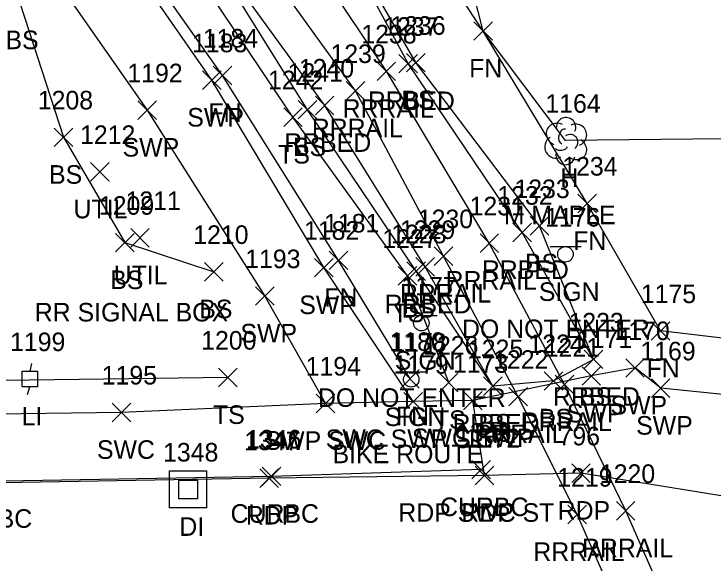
# Model space of a CAD drawing. Extents: x 1715662 to 1717487, y 887396 to 890004.
# Drawn here: x 1716350.8 to 1716426.1, y 888258 to 888317.1 of the extents above; entities that cross this region are included whole.
import ezdxf

# ---------------------------------------------------------------- set-up
doc = ezdxf.new("R2010")
doc.units = 0
for name, color, linetype in [('D_A', 7, 'Continuous'), ('D_I', 7, 'Continuous'), ('DS', 7, 'Continuous'), ('L_A', 7, 'Continuous'), ('L_C', 7, 'Continuous'), ('L_I', 7, 'Continuous'), ('L_TIC', 7, 'Continuous'), ('LELB', 7, 'Continuous'), ('LFNC', 7, 'Continuous'), ('LSOGP', 7, 'Continuous'), ('LTD', 7, 'Continuous'), ('P_A', 7, 'Continuous'), ('P_I', 7, 'Continuous'), ('P_TIC', 7, 'Continuous'), ('PET', 7, 'Continuous'), ('R_A', 7, 'Continuous'), ('R_I', 7, 'Continuous'), ('R_TIC', 7, 'Continuous'), ('RC', 7, 'Continuous'), ('RR', 7, 'Continuous'), ('RRB', 7, 'Continuous'), ('RSW', 7, 'Continuous'), ('S_A', 7, 'Continuous'), ('S_C', 7, 'Continuous'), ('S_I', 7, 'Continuous'), ('SSGN', 7, 'Continuous'), ('U_A', 7, 'Continuous'), ('U_C', 7, 'Continuous'), ('U_I', 7, 'Continuous'), ('UDEFAULT', 7, 'Continuous'), ('ULP', 7, 'Continuous')]:
    doc.layers.add(name, color=color, linetype=linetype)

msp = doc.modelspace()

# ---------------------------------------------------------------- linework, layer by layer
at = {"layer": 'DS'}
for p, q in [((1716367.581, 888267.933), (1716371.581, 888267.933)), ((1716367.581, 888263.933), (1716367.581, 888267.933)), ((1716371.581, 888267.933), (1716371.581, 888263.933)), ((1716368.581, 888264.933), (1716368.581, 888266.933)), ((1716368.581, 888266.933), (1716370.581, 888266.933)), ((1716370.581, 888266.933), (1716370.581, 888264.933)), ((1716369.586, 888265.934), (1716369.586, 888265.934)), ((1716369.586, 888265.934), (1716369.586, 888265.934)), ((1716370.581, 888264.933), (1716368.581, 888264.933)), ((1716371.581, 888263.933), (1716367.581, 888263.933))]:
    msp.add_line(p, q, dxfattribs=at)
at = {"layer": 'L_TIC'}
for points in [[(1716400.348, 888314.282), (1716402.348, 888316.282)], [(1716402.348, 888314.282), (1716400.348, 888316.282)], [(1716393.099, 888310.877), (1716395.099, 888312.877)], [(1716395.099, 888310.877), (1716393.099, 888312.877)], [(1716372.292, 888309.5), (1716374.292, 888311.5)], [(1716374.292, 888309.5), (1716372.292, 888311.5)], [(1716381.432, 888305.814), (1716383.432, 888307.814)], [(1716383.432, 888305.814), (1716381.432, 888307.814)], [(1716379.872, 888305.015), (1716381.872, 888307.015)], [(1716381.872, 888305.015), (1716379.872, 888307.015)], [(1716355.181, 888302.84), (1716357.181, 888304.84)], [(1716357.181, 888302.84), (1716355.181, 888304.84)], [(1716411.543, 888295.715), (1716413.543, 888297.715)], [(1716413.543, 888295.715), (1716411.543, 888297.715)], [(1716406.394, 888293.296), (1716408.394, 888295.296)], [(1716408.394, 888293.296), (1716406.394, 888295.296)], [(1716361.768, 888291.5), (1716363.768, 888293.5)], [(1716363.768, 888291.5), (1716361.768, 888293.5)], [(1716384.773, 888289.591), (1716386.773, 888291.591)], [(1716386.773, 888289.591), (1716384.773, 888291.591)], [(1716371.35, 888288.359), (1716373.35, 888290.359)], [(1716373.35, 888288.359), (1716371.35, 888290.359)], [(1716392.186, 888287.936), (1716394.186, 888289.936)], [(1716394.186, 888287.936), (1716392.186, 888289.936)], [(1716393.13, 888288.432), (1716395.13, 888290.432)], [(1716395.13, 888288.432), (1716393.13, 888290.432)], [(1716419.433, 888281.989), (1716421.433, 888283.989)], [(1716421.433, 888281.989), (1716419.433, 888283.989)], [(1716412.209, 888278.935), (1716414.209, 888280.935)], [(1716414.209, 888278.935), (1716412.209, 888280.935)], [(1716412.209, 888278.935), (1716414.209, 888280.935)], [(1716414.209, 888278.935), (1716412.209, 888280.935)], [(1716372.854, 888276.981), (1716374.854, 888278.981)], [(1716374.854, 888276.981), (1716372.854, 888278.981)], [(1716392.469, 888276.838), (1716394.469, 888278.838)], [(1716394.469, 888276.838), (1716392.469, 888278.838)], [(1716407.898, 888276.608), (1716409.898, 888278.608)], [(1716409.898, 888276.608), (1716407.898, 888278.608)], [(1716396.626, 888276.445), (1716398.626, 888278.445)], [(1716398.626, 888276.445), (1716396.626, 888278.445)], [(1716401.391, 888276.055), (1716403.391, 888278.055)], [(1716403.391, 888276.055), (1716401.391, 888278.055)]]:
    msp.add_lwpolyline(points, dxfattribs=at)
at = {"layer": 'LELB'}
for points in [[(1716397.626, 888277.445), (1716393.186, 888288.936), (1716380.872, 888306.015), (1716367.189, 888326.46), (1716357.094, 888343.322)], [(1716339.091, 888339.822), (1716351.492, 888318.326), (1716356.181, 888303.84), (1716362.768, 888292.5), (1716372.35, 888289.359)], [(1716373.854, 888277.981), (1716341.818, 888277.563), (1716337.074, 888296.382), (1716336.988, 888312.112), (1716344.519, 888320.79), (1716334.379, 888337.453)], [(1716413.209, 888279.935), (1716407.394, 888294.296), (1716394.099, 888311.877), (1716381.094, 888334.374)], [(1716413.209, 888279.935), (1716408.898, 888277.608), (1716402.391, 888277.055), (1716394.13, 888289.432), (1716382.432, 888306.814), (1716369.213, 888328.084)]]:
    msp.add_lwpolyline(points, dxfattribs=at)
at = {"layer": 'LFNC'}
for points in [[(1716443.098, 888280.317), (1716420.433, 888282.989), (1716412.543, 888296.715), (1716401.348, 888315.282), (1716386.51, 888337.853), (1716374.785, 888353.899), (1716358.025, 888375.078), (1716341.376, 888394.001), (1716322.754, 888413.454), (1716303.71, 888431.095), (1716282.224, 888449.189), (1716263.808, 888463.099), (1716243.953, 888476.997), (1716231.603, 888485.189), (1716232.765, 888492.604)], [(1716393.469, 888277.838), (1716385.773, 888290.591), (1716373.292, 888310.5), (1716357.546, 888332.847), (1716346.753, 888347.139), (1716337.883, 888358.435), (1716321.742, 888376.902), (1716305.606, 888393.218), (1716286.544, 888410.885), (1716268.192, 888426.034), (1716248.019, 888441.452), (1716229.393, 888453.959), (1716214.648, 888463.044)]]:
    msp.add_lwpolyline(points, dxfattribs=at)
at = {"layer": 'LSOGP'}
msp.add_lwpolyline([(1716469.007, 888433.308), (1716446.639, 888397.104), (1716439.784, 888394.85), (1716438.641, 888388.155), (1716443.71, 888383.152), (1716446.38, 888343.601), (1716442.786, 888319.775), (1716434.149, 888303.757), (1716410.201, 888303.478), (1716401.342, 888315.278), (1716398.071, 888328.134), (1716386.509, 888337.85), (1716374.78, 888353.896), (1716358.023, 888375.075), (1716341.376, 888394), (1716322.749, 888413.449)], dxfattribs=at)
at = {"layer": 'LTD'}
msp.add_line((1716410.207, 888303.482), (1716410.207, 888303.482), dxfattribs=at)
msp.add_line((1716410.207, 888303.482), (1716410.207, 888303.482), dxfattribs=at)
msp.add_arc((1716410.254, 888304.916), 1.047, 335.52715, 180.95627, dxfattribs=at)
for centre, major_axis, ratio, start_param, end_param in [((1716409.416, 888304.148), (1.21, -0.512), 0.895232, 1.570796, 4.712389), ((1716411.249, 888304.065), (-1.141, -0.483), 0.949671, 1.570796, 4.712389), ((1716409.999, 888303.94), (-0.208, -0.792), 0.645439, 3.141593, 6.283185), ((1716410.707, 888303.315), (-0.5, 0.667), 0.989748, 3.141593, 6.283185), ((1716409.124, 888302.773), (0.584, -1.042), 0.959034, 3.141593, 6.283185), ((1716411.207, 888302.649), (-1.09, 0.792), 0.841452, 1.570796, 4.712389), ((1716409.749, 888302.732), (-0.625, -0.083), 0.423636, 0, 3.141593), ((1716410.208, 888301.982), (0.265, 1.061), 0.942809, 1.570796, 4.712389)]:
    msp.add_ellipse(centre, major_axis=major_axis, ratio=ratio, start_param=start_param, end_param=end_param, dxfattribs=at)
at = {"layer": 'P_TIC'}
for points in [[(1716377.307, 888266.153), (1716379.307, 888268.153)], [(1716379.307, 888266.153), (1716377.307, 888268.153)], [(1716400.494, 888266.443), (1716402.494, 888268.443)], [(1716402.494, 888266.443), (1716400.494, 888268.443)], [(1716410.867, 888266.674), (1716412.867, 888268.674)], [(1716412.867, 888266.674), (1716410.867, 888268.674)]]:
    msp.add_lwpolyline(points, dxfattribs=at)
at = {"layer": 'PET'}
msp.add_lwpolyline([(1716527, 888260.728), (1716516.575, 888259.254), (1716502.433, 888259.092), (1716473.824, 888260.93), (1716440.241, 888263.084), (1716411.867, 888267.674), (1716401.494, 888267.443), (1716378.307, 888267.153), (1716347.525, 888266.611), (1716339.044, 888266.533), (1716305.127, 888265.54), (1716291.61, 888264.06), (1716269.77, 888261.49)], dxfattribs=at)
at = {"layer": 'R_TIC'}
for points in [[(1716392.281, 888310.771), (1716394.281, 888312.771)], [(1716394.281, 888310.771), (1716392.281, 888312.771)], [(1716389.919, 888309.944), (1716391.919, 888311.944)], [(1716391.919, 888309.944), (1716389.919, 888311.944)], [(1716371.137, 888308.995), (1716373.137, 888310.995)], [(1716373.137, 888308.995), (1716371.137, 888310.995)], [(1716386.606, 888307.839), (1716388.606, 888309.839)], [(1716388.606, 888307.839), (1716386.606, 888309.839)], [(1716383.284, 888306.273), (1716385.284, 888308.273)], [(1716385.284, 888306.273), (1716383.284, 888308.273)], [(1716364.176, 888305.762), (1716366.176, 888307.762)], [(1716366.176, 888305.762), (1716364.176, 888307.762)], [(1716404.549, 888292.581), (1716406.549, 888294.581)], [(1716406.549, 888292.581), (1716404.549, 888294.581)], [(1716401.001, 888291.439), (1716403.001, 888293.439)], [(1716403.001, 888291.439), (1716401.001, 888293.439)], [(1716396.082, 888290.053), (1716398.082, 888292.053)], [(1716398.082, 888290.053), (1716396.082, 888292.053)], [(1716383.185, 888288.805), (1716385.185, 888290.805)], [(1716385.185, 888288.805), (1716383.185, 888290.805)], [(1716394.087, 888288.895), (1716396.087, 888290.895)], [(1716396.087, 888288.895), (1716394.087, 888290.895)], [(1716376.856, 888285.753), (1716378.856, 888287.753)], [(1716378.856, 888285.753), (1716376.856, 888287.753)], [(1716412.209, 888278.935), (1716414.209, 888280.935)], [(1716414.209, 888278.935), (1716412.209, 888280.935)], [(1716416.678, 888278.005), (1716418.678, 888280.005)], [(1716418.678, 888278.005), (1716416.678, 888280.005)], [(1716411.978, 888277.145), (1716413.978, 888279.145)], [(1716413.978, 888277.145), (1716411.978, 888279.145)], [(1716401.391, 888276.055), (1716403.391, 888278.055)], [(1716403.391, 888276.055), (1716401.391, 888278.055)], [(1716409.086, 888276.215), (1716411.086, 888278.215)], [(1716411.086, 888276.215), (1716409.086, 888278.215)], [(1716419.44, 888275.827), (1716421.44, 888277.827)], [(1716421.44, 888275.827), (1716419.44, 888277.827)], [(1716392.811, 888274.383), (1716394.811, 888276.383)], [(1716394.811, 888274.383), (1716392.811, 888276.383)], [(1716392.811, 888274.383), (1716394.811, 888276.383)], [(1716394.811, 888274.383), (1716392.811, 888276.383)], [(1716399.217, 888274.488), (1716401.217, 888276.488)], [(1716401.217, 888274.488), (1716399.217, 888276.488)], [(1716399.217, 888274.488), (1716401.217, 888276.488)], [(1716401.217, 888274.488), (1716399.217, 888276.488)], [(1716404.098, 888274.915), (1716406.098, 888276.915)], [(1716406.098, 888274.915), (1716404.098, 888276.915)], [(1716383.363, 888274.19), (1716385.363, 888276.19)], [(1716385.363, 888274.19), (1716383.363, 888276.19)], [(1716383.363, 888274.19), (1716385.363, 888276.19)], [(1716385.363, 888274.19), (1716383.363, 888276.19)], [(1716361.415, 888273.225), (1716363.415, 888275.225)], [(1716363.415, 888273.225), (1716361.415, 888275.225)], [(1716400.116, 888267.058), (1716402.116, 888269.058)], [(1716402.116, 888267.058), (1716400.116, 888269.058)], [(1716377.574, 888266.336), (1716379.574, 888268.336)], [(1716379.574, 888266.336), (1716377.574, 888268.336)], [(1716400.494, 888266.443), (1716402.494, 888268.443)], [(1716402.494, 888266.443), (1716400.494, 888268.443)], [(1716410.445, 888262.23), (1716412.445, 888264.23)], [(1716412.445, 888262.23), (1716410.445, 888264.23)], [(1716415.677, 888262.628), (1716417.677, 888264.628)], [(1716417.677, 888262.628), (1716415.677, 888264.628)]]:
    msp.add_lwpolyline(points, dxfattribs=at)
at = {"layer": 'RC'}
msp.add_lwpolyline([(1716401.116, 888268.058), (1716378.574, 888267.336), (1716347.715, 888266.797), (1716339.127, 888266.78), (1716337.533, 888268.537)], dxfattribs=at)
at = {"layer": 'RR'}
for points in [[(1716436.006, 888215.337), (1716430.823, 888230.215), (1716426.348, 888241.635), (1716416.677, 888263.628), (1716410.086, 888277.215), (1716402.001, 888292.439), (1716390.919, 888310.944), (1716376.876, 888331.991), (1716364.819, 888348.018), (1716349.123, 888367.789), (1716332.642, 888386.349), (1716315.07, 888404.654), (1716296.205, 888422.302), (1716278.069, 888437.86), (1716256.9, 888454.27), (1716238.515, 888467.25), (1716223.556, 888476.476), (1716202.573, 888488.846), (1716178.442, 888501.208), (1716153.561, 888512.412), (1716127.616, 888522.226), (1716099.939, 888531.037), (1716073.491, 888537.688), (1716046.147, 888542.834)], [(1716430.72, 888215.397), (1716425.304, 888230.283), (1716421.076, 888241.431), (1716411.445, 888263.23), (1716405.098, 888275.915), (1716397.082, 888291.053), (1716387.606, 888308.839), (1716372.559, 888329.716), (1716360.984, 888345.241), (1716345.129, 888364.699), (1716328.621, 888383.271), (1716311.711, 888401.255), (1716292.491, 888418.83), (1716274.069, 888433.953), (1716254.21, 888450.025), (1716235.796, 888462.901), (1716221.101, 888472.304), (1716200.717, 888484.158), (1716175.893, 888496.909), (1716151.922, 888507.643), (1716125.759, 888517.559), (1716098.568, 888526.188), (1716072.377, 888532.71), (1716045.904, 888537.783)]]:
    msp.add_lwpolyline(points, dxfattribs=at)
at = {"layer": 'RRB'}
for points in [[(1716413.209, 888279.935), (1716405.549, 888293.581), (1716393.281, 888311.771), (1716381.094, 888334.374), (1716367.434, 888349.07), (1716353.599, 888371.628), (1716336.573, 888389.892), (1716318.547, 888409.005), (1716299.812, 888426.157), (1716280.583, 888443.639), (1716260.294, 888458.826), (1716240.844, 888471.367), (1716225.46, 888478.919)], [(1716402.391, 888277.055), (1716395.087, 888289.895), (1716384.284, 888307.273), (1716369.213, 888328.084), (1716357.094, 888343.322), (1716343.151, 888363.152), (1716325.893, 888380.56), (1716309.064, 888397.835), (1716289.633, 888415.582), (1716271.912, 888431.207), (1716252.081, 888447.529), (1716234.746, 888461.341), (1716219.561, 888469.487)]]:
    msp.add_lwpolyline(points, dxfattribs=at)
at = {"layer": 'RSW'}
for points in [[(1716476.683, 888425.515), (1716468.032, 888388.369), (1716466.749, 888382.232), (1716461.599, 888360.08), (1716450.017, 888310.475), (1716443.843, 888279.7), (1716440.9, 888274.749), (1716420.44, 888276.827), (1716417.678, 888279.005), (1716412.978, 888278.145), (1716400.217, 888275.488)], [(1716393.811, 888275.383), (1716384.185, 888289.805), (1716372.137, 888309.995), (1716356.589, 888332.413), (1716345.321, 888346.931)], [(1716340.33, 888341.332), (1716352.583, 888324.821), (1716365.176, 888306.762), (1716377.856, 888286.753), (1716384.363, 888275.19)], [(1716401.494, 888267.443), (1716400.217, 888275.488), (1716393.811, 888275.383), (1716384.363, 888275.19), (1716362.415, 888274.225), (1716346.221, 888273.995), (1716335.781, 888273.932)]]:
    msp.add_lwpolyline(points, dxfattribs=at)
at = {"layer": 'SSGN'}
for p, q in [((1716408.543, 888292.077), (1716411.877, 888292.077)), ((1716410.19, 888291.244), (1716410.19, 888291.244)), ((1716393.041, 888284.668), (1716396.374, 888284.668)), ((1716394.688, 888283.835), (1716394.688, 888283.835)), ((1716391.95, 888278.607), (1716395.283, 888278.607)), ((1716393.597, 888277.774), (1716393.597, 888277.774))]:
    msp.add_line(p, q, dxfattribs=at)
for centre in [(1716410.19, 888291.244), (1716394.688, 888283.835), (1716393.597, 888277.774)]:
    msp.add_circle(centre, 0.833, dxfattribs=at)
at = {"layer": 'UDEFAULT'}
for points in [[(1716359.085, 888299.12), (1716361.085, 888301.12)], [(1716361.085, 888299.12), (1716359.085, 888301.12)], [(1716363.409, 888292.01), (1716365.409, 888294.01)], [(1716365.409, 888292.01), (1716363.409, 888294.01)]]:
    msp.add_lwpolyline(points, dxfattribs=at)
at = {"layer": 'ULP'}
for p, q in [((1716352.727, 888279.487), (1716352.56, 888278.653)), ((1716351.727, 888276.987), (1716351.727, 888278.653)), ((1716351.727, 888278.653), (1716353.393, 888278.653)), ((1716353.393, 888278.653), (1716353.393, 888276.987)), ((1716352.56, 888277.82), (1716352.56, 888277.82)), ((1716353.393, 888276.987), (1716351.727, 888276.987)), ((1716352.31, 888276.153), (1716352.56, 888276.987))]:
    msp.add_line(p, q, dxfattribs=at)

# ---------------------------------------------------------------- texts
at = {"layer": 'D_A'}
msp.add_text('DI', height=2, dxfattribs=at).set_placement((1716368.641, 888260.934))
at = {"layer": 'D_I'}
msp.add_text('1348', height=2, dxfattribs=at).set_placement((1716366.893, 888268.934))
at = {"layer": 'L_A'}
for s, p in [('BS', (1716349.933, 888313.326)), ('FN', (1716399.829, 888310.282)), ('BS', (1716392.54, 888306.877)), ('FN', (1716371.772, 888305.5)), ('BS', (1716380.873, 888301.814)), ('TS', (1716379.282, 888301.015)), ('BS', (1716354.622, 888298.84)), ('H', (1716409.64, 888298.482)), ('FN', (1716411.023, 888291.715)), ('BS', (1716405.835, 888289.296)), ('BS', (1716361.209, 888287.5)), ('FN', (1716384.253, 888285.591)), ('BS', (1716370.791, 888284.359)), ('BS', (1716392.571, 888284.432)), ('TS', (1716391.595, 888283.936)), ('FN', (1716418.914, 888277.989)), ('BS', (1716411.65, 888274.935)), ('BS', (1716411.65, 888274.935)), ('TS', (1716372.264, 888272.981)), ('FN', (1716391.949, 888272.838)), ('TS', (1716396.036, 888272.445)), ('BS', (1716400.832, 888272.055)), ('BS', (1716407.339, 888272.608))]:
    msp.add_text(s, height=2, dxfattribs=at).set_placement(p)
at = {"layer": 'L_C'}
msp.add_text('M MAPLE', height=2, dxfattribs=at).set_placement((1716403.562, 888294.482))
at = {"layer": 'L_I'}
for s, p in [('1236', (1716391.351, 888314.877)), ('1184', (1716371.166, 888313.5)), ('1241', (1716380.306, 888309.814)), ('1242', (1716378.179, 888309.015)), ('1208', (1716353.409, 888306.84)), ('1164', (1716408.034, 888306.482)), ('1234', (1716409.85, 888299.715)), ('1233', (1716404.701, 888297.296)), ('1209', (1716359.989, 888295.5)), ('1181', (1716384.214, 888293.591)), ('1210', (1716370.138, 888292.359)), ('1228', (1716391.437, 888292.432)), ('1227', (1716390.493, 888291.936)), ('1175', (1716418.307, 888285.989)), ('1223', (1716410.517, 888282.935)), ('1223', (1716410.517, 888282.935)), ('1200', (1716370.996, 888280.981)), ('1180', (1716391.257, 888280.838)), ('1226', (1716394.878, 888280.445)), ('1224', (1716406.205, 888280.608)), ('1225', (1716399.698, 888280.055))]:
    msp.add_text(s, height=2, dxfattribs=at).set_placement(p)
at = {"layer": 'P_A'}
for p in [(1716398.982, 888262.443), (1716409.356, 888262.674), (1716375.795, 888262.153)]:
    msp.add_text('RDP', height=2, dxfattribs=at).set_placement(p)
at = {"layer": 'P_I'}
for s, p in [('1172', (1716399.368, 888270.443)), ('796', (1716409.45, 888270.674)), ('1347', (1716375.614, 888270.153))]:
    msp.add_text(s, height=2, dxfattribs=at).set_placement(p)
at = {"layer": 'R_A'}
for s, p in [('RRBED', (1716388.926, 888306.771)), ('RRRAIL', (1716386.21, 888305.944)), ('SWP', (1716369.499, 888304.995)), ('RRRAIL', (1716382.897, 888303.839)), ('RRBED', (1716379.929, 888302.273)), ('SWP', (1716362.539, 888301.762)), ('RRBED', (1716401.195, 888288.581)), ('RRRAIL', (1716397.292, 888287.439)), ('RRRAIL', (1716392.373, 888286.053)), ('SWP', (1716381.547, 888284.805)), ('RRBED', (1716390.733, 888284.895)), ('SWP', (1716375.218, 888281.753)), ('RRBED', (1716408.855, 888274.935)), ('SWP', (1716415.041, 888274.005)), ('SWP', (1716410.34, 888273.145)), ('RRBED', (1716398.037, 888272.055)), ('RRRAIL', (1716405.377, 888272.215)), ('SWP', (1716417.802, 888271.827)), ('SWC SWP', (1716393.674, 888270.488)), ('SWC SWP', (1716393.674, 888270.488)), ('RRRAIL', (1716400.39, 888270.915)), ('SWP SWC', (1716377.819, 888270.19)), ('SWP SWC', (1716377.819, 888270.19)), ('SWC SWP ST', (1716384.401, 888270.383)), ('SWC SWP ST', (1716384.401, 888270.383)), ('SWC', (1716359.777, 888269.225)), ('CURBC', (1716396.698, 888263.058)), ('CURBC', (1716374.156, 888262.336)), ('RDP SWC ST', (1716392.211, 888262.443)), ('CURBC', (1716343.298, 888261.797)), ('RRRAIL', (1716411.969, 888258.628)), ('RRRAIL', (1716406.736, 888258.23))]:
    msp.add_text(s, height=2, dxfattribs=at).set_placement(p)
at = {"layer": 'R_I'}
for s, p in [('1237', (1716390.588, 888314.771)), ('1238', (1716388.226, 888313.944)), ('1183', (1716370.011, 888312.995)), ('1239', (1716384.905, 888311.839)), ('1192', (1716363.05, 888309.762)), ('1240', (1716381.504, 888310.273)), ('1232', (1716402.856, 888296.581)), ('1231', (1716399.875, 888295.439)), ('1230', (1716394.303, 888294.053)), ('1182', (1716382.059, 888292.805)), ('1229', (1716392.386, 888292.895)), ('1193', (1716375.73, 888289.753)), ('1223', (1716410.517, 888282.935)), ('1170', (1716415.466, 888282.005)), ('1171', (1716411.419, 888281.145)), ('1225', (1716399.698, 888280.055)), ('1221', (1716407.96, 888280.215)), ('1169', (1716418.259, 888279.827)), ('1222', (1716402.405, 888278.915)), ('1194', (1716382.237, 888278.19)), ('1194', (1716382.237, 888278.19)), ('1179', (1716391.677, 888278.383)), ('1179', (1716391.677, 888278.383)), ('1173', (1716398.091, 888278.488)), ('1173', (1716398.091, 888278.488)), ('1195', (1716360.289, 888277.225)), ('1345', (1716398.423, 888271.058)), ('1172', (1716399.368, 888270.443)), ('1346', (1716375.826, 888270.336)), ('1219', (1716409.311, 888266.23)), ('1220', (1716413.898, 888266.628))]:
    msp.add_text(s, height=2, dxfattribs=at).set_placement(p)
at = {"layer": 'S_A'}
for p in [(1716407.328, 888286.223), (1716391.826, 888278.815), (1716390.735, 888272.754)]:
    msp.add_text('SIGN', height=2, dxfattribs=at).set_placement(p)
at = {"layer": 'S_C'}
for s, p in [('DO NOT ENTER', (1716399.06, 888282.223)), ('DO NOT ENTER', (1716383.558, 888274.815)), ('BIKE ROUTE', (1716385.136, 888268.754))]:
    msp.add_text(s, height=2, dxfattribs=at).set_placement(p)
at = {"layer": 'S_I'}
for s, p in [('1176', (1716407.989, 888294.223)), ('1177', (1716392.542, 888286.815)), ('1178', (1716391.451, 888280.754))]:
    msp.add_text(s, height=2, dxfattribs=at).set_placement(p)
at = {"layer": 'U_A'}
for s, p in [('UTIL', (1716357.25, 888295.12)), ('UTIL', (1716361.575, 888288.01)), ('LI', (1716351.662, 888272.82))]:
    msp.add_text(s, height=2, dxfattribs=at).set_placement(p)
at = {"layer": 'U_C'}
msp.add_text('RR SIGNAL BOX', height=2, dxfattribs=at).set_placement((1716353.087, 888284.01))
at = {"layer": 'U_I'}
for s, p in [('1212', (1716357.959, 888303.12)), ('1211', (1716362.85, 888296.01)), ('1199', (1716350.426, 888280.82))]:
    msp.add_text(s, height=2, dxfattribs=at).set_placement(p)

doc.saveas('drawing.dxf')
